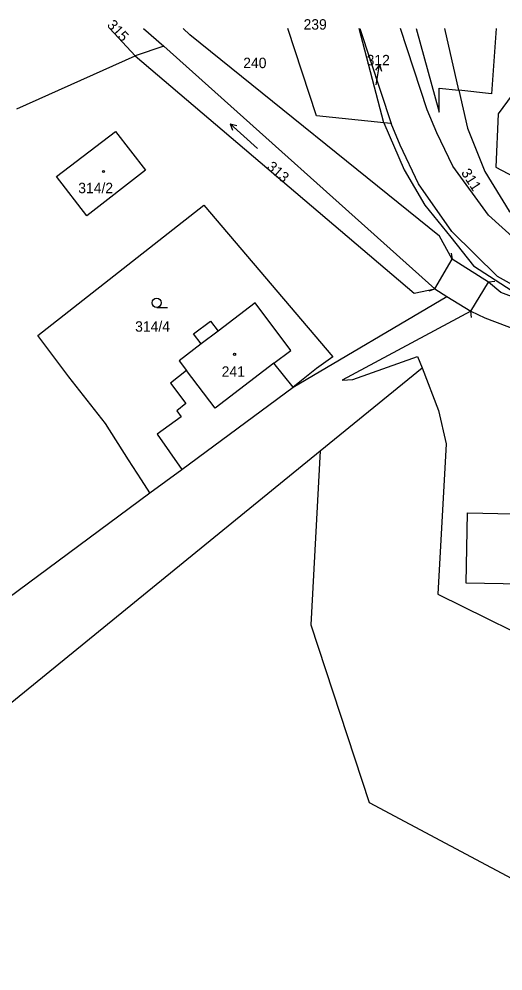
# Model space of a CAD drawing. Extents: x -520431 to -517205, y -1075927 to -1074013.
# Drawn here: x -518114.5 to -518035.5, y -1074168.7 to -1074013.2 of the extents above; entities that cross this region are included whole.
import ezdxf

# ---------------------------------------------------------------- set-up
doc = ezdxf.new("R2010")
doc.units = 0
for name, color, linetype in [('Hranice parcel', 7, 'Continuous'), ('Parcelní čísla', 7, 'Continuous'), ('Pop  PČ popisy', 7, 'Continuous'), ('Vnitřní kresba', 7, 'Continuous'), ('Značky budov', 7, 'Continuous'), ('Značky kultur', 7, 'Continuous')]:
    doc.layers.add(name, color=color, linetype=linetype)

msp = doc.modelspace()

# ---------------------------------------------------------------- linework, layer by layer
at = {"layer": 'Hranice parcel'}
for p, q in [((-518094.16, -1074014.78), (-518090.83, -1074017.65)), ((-518054.93, -1074030.17), (-518058.98, -1074014.78)), ((-518058.86, -1074014.78), (-518053.74, -1074030.31)), ((-518090.83, -1074017.65), (-518095.56, -1074019.24)), ((-518090.83, -1074017.65), (-518046.59, -1074057.28)), ((-518114.84, -1074027.88), (-518095.56, -1074019.24)), ((-518042.66, -1074024.86), (-518041.25, -1074031.07)), ((-518053.74, -1074030.31), (-518054.93, -1074030.17)), ((-518037.82, -1074056.21), (-518043.76, -1074052.46)), ((-518046.59, -1074057.28), (-518044.64, -1074058.57)), ((-518069.76, -1074073.36), (-518044.64, -1074058.57)), ((-518044.64, -1074058.57), (-518040.72, -1074060.96)), ((-518072.9, -1074069.47), (-518070.13, -1074067.35)), ((-518088.37, -1074069.08), (-518087.16, -1074070.66)), ((-518069.76, -1074073.36), (-518072.9, -1074069.47)), ((-518065.32, -1074083.78), (-518048.69, -1074070.23)), ((-518087.92, -1074086.79), (-518069.76, -1074073.36)), ((-518164.48, -1074164.56), (-518065.32, -1074083.78)), ((-518093.12, -1074090.64), (-518087.92, -1074086.79)), ((-518093.12, -1074090.64), (-518094.5, -1074088.5)), ((-518122.83, -1074112.63), (-518093.12, -1074090.64))]:
    msp.add_line(p, q, dxfattribs=at)
for points in [[(-518099.66, -1074014.78), (-518095.56, -1074019.24)], [(-518043.76, -1074052.46), (-518045.85, -1074048.7), (-518086.59, -1074015.8), (-518087.67, -1074014.78)], [(-518054.93, -1074030.17), (-518065.95, -1074029.05), (-518070.61, -1074014.78)], [(-518024.8, -1074054.02), (-518026.36, -1074051.41), (-518027.39, -1074050.82), (-518028.34, -1074052.56), (-518029.28, -1074052.1), (-518033.39, -1074049.28), (-518037.85, -1074045.29), (-518043.66, -1074037.25), (-518046.28, -1074031.8), (-518047.85, -1074028.08), (-518052.23, -1074014.78)], [(-518049.65, -1074014.78), (-518045.9, -1074028.44), (-518045.91, -1074024.5), (-518042.66, -1074024.86)], [(-518036.58, -1074014.78), (-518037.33, -1074025.44), (-518042.66, -1074024.86)], [(-518095.56, -1074019.24), (-518049.96, -1074058.03), (-518046.59, -1074057.28)], [(-518033.22, -1074024.56), (-518036.28, -1074028.73), (-518036.65, -1074037.44), (-518017.96, -1074047.27), (-518012.72, -1074047.85)], [(-518054.93, -1074030.17), (-518051.62, -1074037.84), (-518048.22, -1074043.62), (-518043.98, -1074048.85), (-518040.3, -1074053.57), (-518030.46, -1074059.93)], [(-517889.1, -1074107.75), (-517905.75, -1074096.63), (-517912.05, -1074093.34), (-517923.48, -1074088.82), (-517932.79, -1074086.03), (-517952.8, -1074080.58), (-517993.67, -1074069.35), (-518025.1, -1074060.56), (-518031.6, -1074057.97), (-518036.37, -1074055.31), (-518043.81, -1074047.94), (-518049.25, -1074040.16), (-518052.28, -1074033.84), (-518053.74, -1074030.31)], [(-518093.83, -1074037.93), (-518103.4, -1074045.4), (-518108.36, -1074038.97), (-518098.77, -1074031.58), (-518093.83, -1074037.93)], [(-518041.25, -1074031.07), (-518038.45, -1074038.13), (-518034.49, -1074044.61), (-518029.45, -1074048.27), (-518013.65, -1074055.54)], [(-518094.5, -1074088.5), (-518096.62, -1074085.21), (-518100.4, -1074079.3), (-518106.37, -1074071.68), (-518111.43, -1074064.92), (-518084.31, -1074043.63), (-518063.25, -1074068.41), (-518065.93, -1074070.3), (-518069.76, -1074073.36)], [(-518030.46, -1074059.93), (-518035.83, -1074057.88), (-518037.82, -1074056.21)], [(-518070.13, -1074067.35), (-518075.96, -1074059.57), (-518082, -1074064.2), (-518084.74, -1074066.3), (-518088.37, -1074069.08)], [(-518040.72, -1074060.96), (-518061.72, -1074072.22), (-518060, -1074072.1), (-518049.43, -1074068.34), (-518048.69, -1074070.23)], [(-518040.72, -1074060.96), (-518038.45, -1074062.02), (-518025.19, -1074067.07)], [(-518087.16, -1074070.66), (-518089.76, -1074072.71), (-518087.25, -1074076.01), (-518088.75, -1074077.21), (-518088.01, -1074078.19), (-518091.92, -1074081.04), (-518087.92, -1074086.79)], [(-518048.69, -1074070.23), (-518045.98, -1074077.16), (-518044.75, -1074082.64), (-518046.09, -1074107.18), (-518026.01, -1074117.1)], [(-518065.32, -1074083.78), (-518066.87, -1074112.18), (-518057.33, -1074141.22), (-518030.78, -1074155.34), (-517973.95, -1074168.72)], [(-518023.42, -1074105.69), (-518041.47, -1074105.37), (-518041.29, -1074093.91), (-518033.81, -1074094.04), (-518033.76, -1074091.82), (-518030.57, -1074091.9), (-518030.6, -1074094.09), (-518023.21, -1074094.2), (-518023.4, -1074102.57)]]:
    msp.add_lwpolyline(points, dxfattribs=at)
at = {"layer": 'Pop  PČ popisy'}
for p, q in [((-518055.66, -1074020.69), (-518056.31, -1074021.6)), ((-518056.13, -1074023.65), (-518055.66, -1074020.69)), ((-518055.66, -1074020.69), (-518055.32, -1074021.75)), ((-518056.19, -1074024), (-518056.13, -1074023.65))]:
    msp.add_line(p, q, dxfattribs=at)
at = {"layer": 'Vnitřní kresba'}
for p, q in [((-518042.66, -1074024.86), (-518044.95, -1074014.78)), ((-518043.93, -1074051.48), (-518043.76, -1074052.46)), ((-518046.59, -1074057.28), (-518043.76, -1074052.46)), ((-518040.72, -1074060.96), (-518037.82, -1074056.21)), ((-518036.83, -1074056.09), (-518037.82, -1074056.21)), ((-518047.52, -1074057.64), (-518046.59, -1074057.28)), ((-518040.63, -1074061.96), (-518040.72, -1074060.96)), ((-518085.99, -1074064.67), (-518083.23, -1074062.59)), ((-518083.23, -1074062.59), (-518082, -1074064.2)), ((-518084.74, -1074066.3), (-518085.99, -1074064.67)), ((-518082.47, -1074076.79), (-518087.16, -1074070.66)), ((-518072.9, -1074069.47), (-518082.47, -1074076.79))]:
    msp.add_line(p, q, dxfattribs=at)
at = {"layer": 'Značky budov'}
for centre in [(-518100.71, -1074038.13), (-518079.3, -1074067.99)]:
    msp.add_circle(centre, 0.175, dxfattribs=at)
at = {"layer": 'Značky kultur'}
for p, q in [((-518075.56, -1074034.37), (-518080.02, -1074030.35)), ((-518080.02, -1074030.35), (-518079.63, -1074031.38)), ((-518080.02, -1074030.35), (-518078.96, -1074030.64)), ((-518092.02, -1074060.33), (-518090.27, -1074060.33))]:
    msp.add_line(p, q, dxfattribs=at)
msp.add_circle((-518092.02, -1074059.58), 0.75, dxfattribs=at)

# ---------------------------------------------------------------- texts
at = {"layer": 'Parcelní čísla'}
for s, rotation, p in [('315', 313, (-518100.24, -1074014.3)), ('313', 319, (-518074.19, -1074037.58)), ('311', 303, (-518042.39, -1074038.33))]:
    msp.add_text(s, height=1.7, rotation=rotation, dxfattribs=at).set_placement(p)
for s, p in [('239', (-518068.04, -1074014.96)), ('240', (-518077.89, -1074021.25)), ('312', (-518057.74, -1074020.79)), ('314/2', (-518104.83, -1074041.68)), ('314/4', (-518095.54, -1074064.3)), ('241', (-518081.41, -1074071.66))]:
    msp.add_text(s, height=1.7, dxfattribs=at).set_placement(p)

doc.saveas('drawing.dxf')
